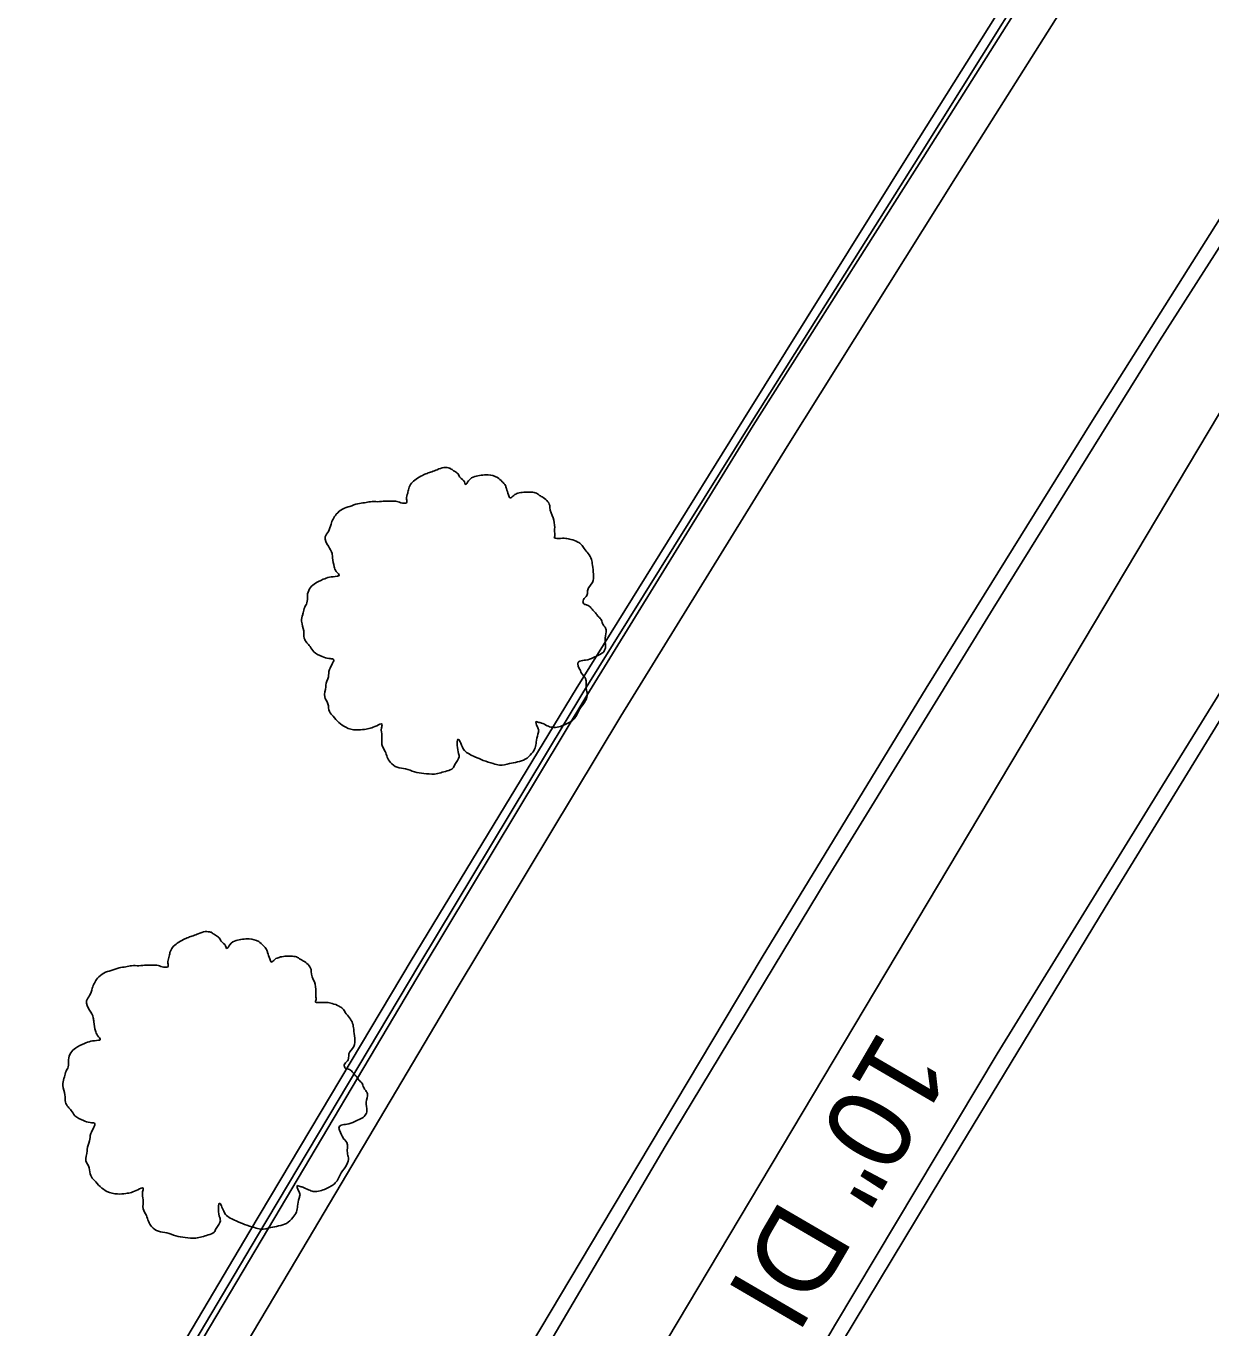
# Model space of a CAD drawing. Extents: x 2004847 to 2009016, y 1134161 to 1140101.
# Drawn here: x 2007878.5 to 2007934.9, y 1139100.8 to 1139162.8 of the extents above; entities that cross this region are included whole.
import ezdxf

# ---------------------------------------------------------------- set-up
doc = ezdxf.new("R2010")
doc.units = 0
for name, color, linetype in [('RD_EX_Curb', 7, 'Continuous'), ('RD_EX_Pavement_Markings', 7, 'Continuous'), ('RD_EX_Road', 7, 'Continuous'), ('RD_EX_UT', 7, 'Continuous'), ('RD_EX_VEG', 7, 'Continuous'), ('RD_Sketch2', 7, 'Continuous')]:
    doc.layers.add(name, color=color, linetype=linetype)

msp = doc.modelspace()

# ---------------------------------------------------------------- linework, layer by layer
at = {"layer": 'RD_EX_Curb'}
for points in [[(2007851.738, 1139039.762), (2007859.238, 1139052.983), (2007866.607, 1139066.108), (2007873.994, 1139079.284), (2007881.459, 1139092.399), (2007889.186, 1139105.435), (2007896.871, 1139118.33), (2007904.719, 1139131.268), (2007912.686, 1139144.101), (2007920.684, 1139156.928), (2007928.661, 1139169.637), (2007936.888, 1139182.444), (2007945.175, 1139194.942), (2007953.654, 1139207.519), (2007962.071, 1139219.981), (2007965.836, 1139225.497)], [(2007852.173, 1139039.527), (2007859.641, 1139052.758), (2007866.98, 1139065.898), (2007874.366, 1139079.072), (2007881.83, 1139092.183), (2007889.554, 1139105.216), (2007897.239, 1139118.11), (2007905.035, 1139131.075), (2007913.022, 1139143.893), (2007921.074, 1139156.681), (2007929.037, 1139169.399), (2007937.26, 1139182.2), (2007945.52, 1139194.715), (2007954.01, 1139207.279), (2007962.419, 1139219.745), (2007966.163, 1139225.272)], [(2007852.399, 1139039.406), (2007859.85, 1139052.642), (2007867.203, 1139065.772), (2007874.587, 1139078.945), (2007882.05, 1139092.055), (2007889.774, 1139105.085), (2007897.437, 1139117.992), (2007905.232, 1139130.955), (2007913.155, 1139143.81), (2007921.234, 1139156.58), (2007929.246, 1139169.267), (2007937.467, 1139182.064), (2007945.719, 1139194.584), (2007954.174, 1139207.169), (2007962.603, 1139219.62), (2007966.32, 1139225.164)]]:
    msp.add_lwpolyline(points, dxfattribs=at)
at = {"layer": 'RD_EX_Pavement_Markings'}
for points in [[(2007820.157, 1138947.398), (2007826.834, 1138960.83), (2007833.554, 1138974.241), (2007840.428, 1138987.573), (2007847.335, 1139000.888), (2007854.38, 1139014.13), (2007861.469, 1139027.35), (2007868.587, 1139040.553), (2007875.888, 1139053.657), (2007883.239, 1139066.732), (2007890.688, 1139079.751), (2007898.221, 1139092.723), (2007905.895, 1139105.611), (2007913.581, 1139118.493), (2007921.389, 1139131.3), (2007929.294, 1139144.048), (2007937.306, 1139156.729), (2007945.328, 1139169.404), (2007953.554, 1139181.947), (2007961.784, 1139194.488), (2007970.174, 1139206.922), (2007977.391, 1139217.536)], [(2007973.46, 1139210.655), (2007965.166, 1139198.157), (2007956.871, 1139185.659), (2007948.649, 1139173.114), (2007940.568, 1139160.477), (2007932.487, 1139147.839), (2007924.572, 1139135.098), (2007916.725, 1139122.314), (2007908.966, 1139109.476), (2007901.359, 1139096.548), (2007893.752, 1139083.621), (2007886.252, 1139070.63), (2007878.887, 1139057.563), (2007871.558, 1139044.475), (2007864.404, 1139031.291), (2007857.279, 1139018.091), (2007850.195, 1139004.87), (2007843.293, 1138991.551), (2007836.392, 1138978.233)], [(2007986.725, 1139209.149), (2007978.402, 1139196.67), (2007970.159, 1139184.138), (2007961.961, 1139171.577), (2007953.796, 1139158.993), (2007945.771, 1139146.32), (2007937.747, 1139133.647), (2007929.91, 1139120.857), (2007922.124, 1139108.037), (2007914.381, 1139095.189), (2007906.86, 1139082.211), (2007899.34, 1139069.233), (2007891.954, 1139056.177), (2007884.577, 1139043.116), (2007877.351, 1139029.971), (2007870.184, 1139016.794), (2007863.132, 1139003.555), (2007856.118, 1138990.296), (2007849.256, 1138976.958), (2007842.455, 1138963.588), (2007835.737, 1138950.177)], [(2007831.323, 1138942.803), (2007838.008, 1138956.231), (2007844.727, 1138969.642), (2007851.637, 1138982.956), (2007858.546, 1138996.27), (2007865.517, 1139009.552), (2007872.675, 1139022.734), (2007879.833, 1139035.916), (2007887.173, 1139048.997), (2007894.569, 1139062.047), (2007901.965, 1139075.097), (2007909.482, 1139088.077), (2007917.07, 1139101.016), (2007924.766, 1139113.892), (2007932.638, 1139126.66), (2007940.526, 1139139.418), (2007948.573, 1139152.078), (2007956.668, 1139164.706), (2007964.824, 1139177.294), (2007973.078, 1139189.819), (2007983.117, 1139205.05)]]:
    msp.add_lwpolyline(points, dxfattribs=at)
at = {"layer": 'RD_EX_Road'}
msp.add_lwpolyline([(2007854.063, 1139038.509), (2007861.505, 1139051.719), (2007868.855, 1139064.844), (2007876.232, 1139078.004), (2007883.689, 1139091.103), (2007891.402, 1139104.116), (2007899.064, 1139117.021), (2007906.851, 1139129.969), (2007914.766, 1139142.812), (2007922.773, 1139155.607), (2007930.784, 1139168.293), (2007938.99, 1139181.066), (2007947.297, 1139193.549), (2007955.758, 1139206.099), (2007964.183, 1139218.545), (2007967.911, 1139224.067)], dxfattribs=at)
at = {"layer": 'RD_EX_UT'}
msp.add_line((2007865.163, 1139026.691), (2007964.711, 1139193.633), dxfattribs=at)
at = {"layer": 'RD_EX_VEG'}
for points in [[(2007898.727, 1139141.782), (2007898.427, 1139141.807), (2007898.102, 1139141.707), (2007897.852, 1139141.607), (2007897.627, 1139141.532), (2007897.402, 1139141.432), (2007897.103, 1139141.257), (2007896.878, 1139141.057), (2007896.753, 1139140.808), (2007896.703, 1139140.583), (2007896.653, 1139140.308), (2007896.653, 1139140.133), (2007896.528, 1139140.108), (2007896.378, 1139140.133), (2007896.128, 1139140.208), (2007895.878, 1139140.208), (2007895.628, 1139140.208), (2007895.278, 1139140.183), (2007894.928, 1139140.183), (2007894.654, 1139140.133), (2007894.329, 1139140.083), (2007893.954, 1139139.958), (2007893.604, 1139139.833), (2007893.304, 1139139.583), (2007893.054, 1139139.108), (2007892.929, 1139138.759), (2007892.779, 1139138.509), (2007892.929, 1139138.059), (2007893.104, 1139137.709), (2007893.129, 1139137.509), (2007893.204, 1139137.084), (2007893.304, 1139136.859), (2007893.429, 1139136.659), (2007893.354, 1139136.634), (2007892.979, 1139136.584), (2007892.679, 1139136.485), (2007892.255, 1139136.26), (2007892.03, 1139136.035), (2007891.93, 1139135.71), (2007891.905, 1139135.36), (2007891.805, 1139135.16), (2007891.73, 1139134.885), (2007891.705, 1139134.81), (2007891.655, 1139134.485), (2007891.755, 1139134.036), (2007891.78, 1139133.686), (2007891.905, 1139133.461), (2007892.055, 1139133.286), (2007892.23, 1139133.036), (2007892.629, 1139132.811), (2007892.954, 1139132.711), (2007893.154, 1139132.686), (2007892.979, 1139132.186), (2007892.929, 1139131.837), (2007892.804, 1139131.437), (2007892.804, 1139131.362), (2007892.754, 1139130.887), (2007892.904, 1139130.562), (2007892.979, 1139130.187), (2007893.154, 1139129.962), (2007893.429, 1139129.662), (2007893.754, 1139129.438), (2007894.254, 1139129.313), (2007894.654, 1139129.338), (2007895.228, 1139129.513), (2007895.478, 1139129.588), (2007895.453, 1139129.413), (2007895.478, 1139129.038), (2007895.478, 1139128.613), (2007895.628, 1139128.288), (2007895.728, 1139128.013), (2007895.878, 1139127.763), (2007896.203, 1139127.538), (2007896.603, 1139127.463), (2007897.028, 1139127.314), (2007897.477, 1139127.239), (2007897.977, 1139127.214), (2007898.577, 1139127.363), (2007898.852, 1139127.488), (2007898.952, 1139127.663), (2007899.152, 1139128.038), (2007899.102, 1139128.263), (2007899.127, 1139128.863), (2007899.227, 1139128.688), (2007899.402, 1139128.338), (2007899.901, 1139128.038), (2007900.301, 1139127.863), (2007900.776, 1139127.713), (2007901.076, 1139127.638), (2007901.551, 1139127.713), (2007901.925, 1139127.788), (2007902.3, 1139127.913), (2007902.6, 1139128.188), (2007902.775, 1139128.463), (2007902.825, 1139128.738), (2007902.9, 1139129.113), (2007902.95, 1139129.288)], [(2007902.95, 1139129.288), (2007902.875, 1139129.463), (2007902.825, 1139129.712), (2007902.9, 1139129.687), (2007903.075, 1139129.637), (2007903.35, 1139129.513), (2007903.575, 1139129.438), (2007903.9, 1139129.463), (2007904.174, 1139129.563), (2007904.624, 1139129.837), (2007904.899, 1139130.312), (2007905.174, 1139130.712), (2007905.249, 1139131.037), (2007905.199, 1139131.262), (2007905.174, 1139131.762), (2007904.974, 1139132.011), (2007904.924, 1139132.136), (2007904.824, 1139132.536), (2007904.899, 1139132.586), (2007905.174, 1139132.636), (2007905.549, 1139132.761), (2007905.824, 1139132.886), (2007906.049, 1139133.061), (2007906.124, 1139133.286), (2007906.099, 1139133.686), (2007906.149, 1139134.086), (2007906.074, 1139134.236), (2007905.974, 1139134.385), (2007905.899, 1139134.585), (2007905.749, 1139134.735), (2007905.649, 1139134.885), (2007905.549, 1139134.985), (2007905.424, 1139135.135), (2007905.249, 1139135.26), (2007905.099, 1139135.31), (2007905.049, 1139135.46), (2007905.199, 1139135.66), (2007905.249, 1139135.76), (2007905.274, 1139135.985), (2007905.499, 1139136.335), (2007905.549, 1139136.734), (2007905.499, 1139137.159), (2007905.449, 1139137.434), (2007905.299, 1139137.709), (2007905.099, 1139137.959), (2007904.974, 1139138.134), (2007904.799, 1139138.259), (2007904.474, 1139138.384), (2007904.224, 1139138.434), (2007903.875, 1139138.434), (2007903.675, 1139138.484), (2007903.7, 1139138.534), (2007903.7, 1139138.684), (2007903.7, 1139138.958), (2007903.625, 1139139.408), (2007903.475, 1139139.908), (2007903.475, 1139139.933), (2007903.375, 1139140.183), (2007903.15, 1139140.383), (2007902.975, 1139140.483), (2007902.775, 1139140.608), (2007902.525, 1139140.633), (2007902.225, 1139140.633), (2007901.95, 1139140.583), (2007901.75, 1139140.483), (2007901.576, 1139140.358), (2007901.501, 1139140.508), (2007901.401, 1139140.808), (2007901.351, 1139140.958), (2007901.201, 1139141.132), (2007900.976, 1139141.332), (2007900.526, 1139141.457), (2007899.901, 1139141.382), (2007899.601, 1139141.182), (2007899.451, 1139141.008), (2007899.402, 1139141.132), (2007899.202, 1139141.332), (2007899.102, 1139141.507), (2007898.927, 1139141.632), (2007898.777, 1139141.732), (2007898.677, 1139141.782)], [(2007887.361, 1139119.683), (2007887.061, 1139119.708), (2007886.736, 1139119.608), (2007886.486, 1139119.508), (2007886.261, 1139119.433), (2007886.036, 1139119.333), (2007885.737, 1139119.158), (2007885.512, 1139118.958), (2007885.387, 1139118.708), (2007885.337, 1139118.483), (2007885.287, 1139118.209), (2007885.287, 1139118.034), (2007885.162, 1139118.009), (2007885.012, 1139118.034), (2007884.762, 1139118.109), (2007884.512, 1139118.109), (2007884.262, 1139118.109), (2007883.912, 1139118.084), (2007883.562, 1139118.084), (2007883.288, 1139118.034), (2007882.963, 1139117.984), (2007882.588, 1139117.859), (2007882.238, 1139117.734), (2007881.938, 1139117.484), (2007881.688, 1139117.009), (2007881.563, 1139116.659), (2007881.413, 1139116.409), (2007881.563, 1139115.96), (2007881.738, 1139115.61), (2007881.763, 1139115.41), (2007881.838, 1139114.985), (2007881.938, 1139114.76), (2007882.063, 1139114.56), (2007881.988, 1139114.535), (2007881.613, 1139114.485), (2007881.313, 1139114.385), (2007880.889, 1139114.16), (2007880.664, 1139113.935), (2007880.564, 1139113.61), (2007880.539, 1139113.261), (2007880.439, 1139113.061), (2007880.364, 1139112.786), (2007880.339, 1139112.711), (2007880.289, 1139112.386), (2007880.389, 1139111.936), (2007880.414, 1139111.586), (2007880.539, 1139111.361), (2007880.689, 1139111.187), (2007880.864, 1139110.937), (2007881.263, 1139110.712), (2007881.588, 1139110.612), (2007881.788, 1139110.587), (2007881.613, 1139110.087), (2007881.563, 1139109.737), (2007881.438, 1139109.337), (2007881.438, 1139109.262), (2007881.388, 1139108.788), (2007881.538, 1139108.463), (2007881.613, 1139108.088), (2007881.788, 1139107.863), (2007882.063, 1139107.563), (2007882.388, 1139107.338), (2007882.888, 1139107.213), (2007883.288, 1139107.238), (2007883.862, 1139107.413), (2007884.112, 1139107.488), (2007884.087, 1139107.313), (2007884.112, 1139106.938), (2007884.112, 1139106.514), (2007884.262, 1139106.189), (2007884.362, 1139105.914), (2007884.512, 1139105.664), (2007884.837, 1139105.439), (2007885.237, 1139105.364), (2007885.662, 1139105.214), (2007886.111, 1139105.139), (2007886.611, 1139105.114), (2007887.211, 1139105.264), (2007887.486, 1139105.389), (2007887.586, 1139105.564), (2007887.786, 1139105.939), (2007887.736, 1139106.164), (2007887.761, 1139106.764), (2007887.861, 1139106.589), (2007888.036, 1139106.239), (2007888.535, 1139105.939), (2007888.935, 1139105.764), (2007889.41, 1139105.614), (2007889.71, 1139105.539), (2007890.185, 1139105.614), (2007890.559, 1139105.689), (2007890.934, 1139105.814), (2007891.234, 1139106.089), (2007891.409, 1139106.364), (2007891.459, 1139106.639), (2007891.534, 1139107.013), (2007891.584, 1139107.188)], [(2007891.584, 1139107.188), (2007891.509, 1139107.363), (2007891.459, 1139107.613), (2007891.534, 1139107.588), (2007891.709, 1139107.538), (2007891.984, 1139107.413), (2007892.209, 1139107.338), (2007892.534, 1139107.363), (2007892.808, 1139107.463), (2007893.258, 1139107.738), (2007893.533, 1139108.213), (2007893.808, 1139108.613), (2007893.883, 1139108.938), (2007893.833, 1139109.162), (2007893.808, 1139109.662), (2007893.608, 1139109.912), (2007893.558, 1139110.037), (2007893.458, 1139110.437), (2007893.533, 1139110.487), (2007893.808, 1139110.537), (2007894.183, 1139110.662), (2007894.458, 1139110.787), (2007894.683, 1139110.962), (2007894.758, 1139111.187), (2007894.733, 1139111.586), (2007894.783, 1139111.986), (2007894.708, 1139112.136), (2007894.608, 1139112.286), (2007894.533, 1139112.486), (2007894.383, 1139112.636), (2007894.283, 1139112.786), (2007894.183, 1139112.886), (2007894.058, 1139113.036), (2007893.883, 1139113.161), (2007893.733, 1139113.211), (2007893.683, 1139113.361), (2007893.833, 1139113.561), (2007893.883, 1139113.66), (2007893.908, 1139113.885), (2007894.133, 1139114.235), (2007894.183, 1139114.635), (2007894.133, 1139115.06), (2007894.083, 1139115.335), (2007893.933, 1139115.61), (2007893.733, 1139115.86), (2007893.608, 1139116.034), (2007893.433, 1139116.159), (2007893.108, 1139116.284), (2007892.858, 1139116.334), (2007892.509, 1139116.334), (2007892.309, 1139116.384), (2007892.334, 1139116.434), (2007892.334, 1139116.584), (2007892.334, 1139116.859), (2007892.259, 1139117.309), (2007892.109, 1139117.809), (2007892.109, 1139117.834), (2007892.009, 1139118.084), (2007891.784, 1139118.283), (2007891.609, 1139118.383), (2007891.409, 1139118.508), (2007891.159, 1139118.533), (2007890.859, 1139118.533), (2007890.584, 1139118.483), (2007890.384, 1139118.383), (2007890.21, 1139118.258), (2007890.135, 1139118.408), (2007890.035, 1139118.708), (2007889.985, 1139118.858), (2007889.835, 1139119.033), (2007889.61, 1139119.233), (2007889.16, 1139119.358), (2007888.535, 1139119.283), (2007888.235, 1139119.083), (2007888.085, 1139118.908), (2007888.036, 1139119.033), (2007887.836, 1139119.233), (2007887.736, 1139119.408), (2007887.561, 1139119.533), (2007887.411, 1139119.633), (2007887.311, 1139119.683)]]:
    msp.add_spline(points, degree=3, dxfattribs=at)

# ---------------------------------------------------------------- texts
at = {"layer": 'RD_Sketch2'}
msp.add_text('10" DI', height=4, rotation=239.72357, dxfattribs=at).set_placement((2007919.213, 1139115.15))

doc.saveas('drawing.dxf')
